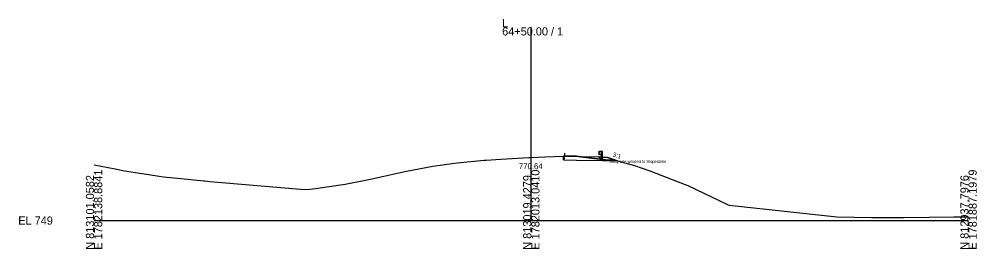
# Model space of a CAD drawing. Extents: x -26 to 7903, y -10 to 9573.
# Drawn here: x 2974.3 to 3302.8, y 5490.3 to 5569.1 of the extents above; entities that cross this region are included whole.
import ezdxf

# ---------------------------------------------------------------- set-up
doc = ezdxf.new("R2010")
doc.units = 0
for name, color, linetype in [('Exist Cross Section Cell', 7, 'Continuous'), ('Exist XS Center Line Elevation Label', 7, 'Continuous'), ('Exist XS Ground Line', 7, 'Continuous'), ('Prop XS Dump Level', 7, 'Continuous'), ('Prop XS Earthwork Shape', 7, 'Continuous'), ('Prop XS EOT Tick Mark', 7, 'Continuous'), ('Prop XS Finish Grade', 7, 'Continuous'), ('Prop XS Finish Grade Paved Shoulder', 7, 'Continuous'), ('Prop XS Finish Grade Pavement', 7, 'Continuous'), ('Prop XS Guardrail', 7, 'Continuous'), ('Prop XS Pvmt Edge Slope', 7, 'Continuous'), ('Prop XS Side Slope Text', 7, 'Continuous'), ('Prop XS Subgrade Earthwork', 7, 'Continuous'), ('Scratch_Level_3', 7, 'Continuous'), ('Scratch_Level_6', 7, 'Continuous')]:
    doc.layers.add(name, color=color, linetype=linetype)

msp = doc.modelspace()

# ---------------------------------------------------------------- linework, layer by layer
at = {"layer": 'Exist Cross Section Cell'}
for p, q in [((3150, 5500), (3150, 5566.27)), ((3000, 5500), (3150, 5500)), ((3150, 5500), (3300, 5500))]:
    msp.add_line(p, q, dxfattribs=at)
at = {"layer": 'Exist XS Ground Line'}
for p, q in [((3116.2, 5518.7), (3122.85, 5519.59)), ((3122.85, 5519.59), (3124.55, 5519.82)), ((3124.55, 5519.82), (3133.81, 5520.69)), ((3133.81, 5520.69), (3134.51, 5520.76)), ((3134.51, 5520.76), (3137.82, 5520.97)), ((3137.82, 5520.97), (3139.5, 5521.07)), ((3139.5, 5521.07), (3149.11, 5521.6)), ((3149.11, 5521.6), (3150, 5521.64)), ((3150, 5521.64), (3154.69, 5521.83)), ((3154.69, 5521.83), (3161.1, 5522.09)), ((3161.1, 5522.09), (3165.47, 5522.06)), ((3165.47, 5522.06), (3167.03, 5521.87)), ((3167.03, 5521.87), (3175.42, 5520.78)), ((3175.42, 5520.78), (3177.55, 5520.76)), ((3177.55, 5520.76), (3179.56, 5520.5)), ((3179.56, 5520.5), (3185.36, 5518.9)), ((3000, 5519.06), (3007.27, 5517.71)), ((3007.27, 5517.71), (3010.5, 5517.05)), ((3010.5, 5517.05), (3020.95, 5515.41)), ((3097.36, 5514.79), (3104.6, 5516.41)), ((3104.6, 5516.41), (3107.21, 5516.94)), ((3107.21, 5516.94), (3116.2, 5518.7)), ((3185.36, 5518.9), (3190.7, 5517.07)), ((3190.7, 5517.07), (3200.43, 5513.27)), ((3020.95, 5515.41), (3022.39, 5515.17)), ((3022.39, 5515.17), (3023.81, 5515.02)), ((3023.81, 5515.02), (3029.79, 5514.43)), ((3029.79, 5514.43), (3037.65, 5513.64)), ((3037.65, 5513.64), (3037.99, 5513.62)), ((3037.99, 5513.62), (3038.92, 5513.53)), ((3038.92, 5513.53), (3039.76, 5513.45)), ((3039.76, 5513.45), (3043.87, 5513.08)), ((3043.87, 5513.08), (3070.77, 5510.72)), ((3086.11, 5512.54), (3094.25, 5514.12)), ((3094.25, 5514.12), (3094.88, 5514.23)), ((3094.88, 5514.23), (3097.36, 5514.79)), ((3200.43, 5513.27), (3203.64, 5512.04)), ((3070.77, 5510.72), (3072.99, 5510.6)), ((3072.99, 5510.6), (3075.97, 5511.05)), ((3075.97, 5511.05), (3086.11, 5512.54)), ((3203.64, 5512.04), (3217.27, 5505.53)), ((3217.27, 5505.53), (3217.85, 5505.29)), ((3217.85, 5505.29), (3254.79, 5501.33)), ((3254.79, 5501.33), (3266.74, 5501.09)), ((3266.74, 5501.09), (3277.72, 5501.04)), ((3277.72, 5501.04), (3286.52, 5501.2)), ((3286.52, 5501.2), (3294.96, 5501.25)), ((3294.96, 5501.25), (3300, 5501.29))]:
    msp.add_line(p, q, dxfattribs=at)
at = {"layer": 'Prop XS Dump Level'}
for p, q in [((3161.14, 5521.42), (3161.47, 5521.41)), ((3161.47, 5521.41), (3161.14, 5521.42))]:
    msp.add_line(p, q, dxfattribs=at)
at = {"layer": 'Prop XS Earthwork Shape'}
msp.add_lwpolyline([(3161.1, 5520.84), (3161.47, 5520.85), (3165.47, 5520.77), (3174.38, 5520.59), (3179.56, 5520.5), (3177.55, 5520.76), (3175.42, 5520.78), (3167.03, 5521.87), (3165.47, 5522.06), (3161.1, 5522.09)], close=True, dxfattribs=at)
at = {"layer": 'Prop XS EOT Tick Mark'}
msp.add_line((3161.47, 5522.1), (3161.47, 5523.1), dxfattribs=at)
at = {"layer": 'Prop XS Finish Grade'}
for p, q in [((3173.1, 5521.87), (3176.1, 5521.63)), ((3176.1, 5521.63), (3179.56, 5520.5))]:
    msp.add_line(p, q, dxfattribs=at)
at = {"layer": 'Prop XS Finish Grade Paved Shoulder'}
msp.add_line((3161.47, 5522.1), (3173.1, 5521.87), dxfattribs=at)
at = {"layer": 'Prop XS Finish Grade Pavement'}
msp.add_line((3161.1, 5522.09), (3161.47, 5522.1), dxfattribs=at)
at = {"layer": 'Prop XS Guardrail'}
for p, q in [((3173.13, 5523.54), (3173.1, 5523.48)), ((3173.1, 5523.48), (3173.13, 5523.42)), ((3173.13, 5522.93), (3173.1, 5522.87)), ((3173.1, 5522.87), (3173.13, 5522.81)), ((3173.42, 5523.74), (3173.13, 5523.54)), ((3173.13, 5523.42), (3173.42, 5523.22)), ((3173.42, 5523.13), (3173.13, 5522.93)), ((3173.13, 5522.81), (3173.42, 5522.61)), ((3173.92, 5523.74), (3173.42, 5523.74)), ((3173.42, 5523.22), (3173.42, 5523.13)), ((3174.42, 5523.74), (3173.92, 5523.74)), ((3173.92, 5523.74), (3173.92, 5521.24)), ((3174.42, 5521.24), (3174.42, 5523.74)), ((3173.42, 5522.61), (3173.92, 5522.61))]:
    msp.add_line(p, q, dxfattribs=at)
at = {"layer": 'Prop XS Pvmt Edge Slope'}
msp.add_line((3173.1, 5521.87), (3174.38, 5520.59), dxfattribs=at)
at = {"layer": 'Prop XS Subgrade Earthwork'}
for p, q in [((3161.1, 5520.84), (3161.1, 5522.09)), ((3161.1, 5520.84), (3161.47, 5520.85)), ((3161.47, 5520.85), (3165.47, 5520.77)), ((3165.47, 5520.77), (3174.38, 5520.59)), ((3174.38, 5520.59), (3179.56, 5520.5))]:
    msp.add_line(p, q, dxfattribs=at)
at = {"layer": 'Scratch_Level_3'}
for p, q in [((3176.1, 5521.63), (3173.1, 5521.87)), ((3173.1, 5521.87), (3174.38, 5520.59)), ((3174.38, 5520.59), (3179.56, 5520.5)), ((3179.56, 5520.5), (3176.1, 5521.63))]:
    msp.add_line(p, q, dxfattribs=at)
at = {"layer": 'Scratch_Level_6'}
for points in [[(3161.1, 5520.84), (3161.47, 5520.85), (3165.47, 5520.77), (3174.38, 5520.59), (3179.56, 5520.5), (3177.55, 5520.76), (3175.42, 5520.78), (3167.03, 5521.87), (3165.84, 5522.02), (3162.68, 5522.08), (3161.1, 5522.09)], [(3162.68, 5522.08), (3165.84, 5522.02), (3165.47, 5522.06)]]:
    msp.add_lwpolyline(points, close=True, dxfattribs=at)

# ---------------------------------------------------------------- texts
at = {"layer": 'Exist Cross Section Cell'}
for s, p in [('L', (3140, 5566.27)), ('64+50.00 / 1', (3140, 5563.47)), ('EL 749', (2974, 5498.6))]:
    msp.add_text(s, height=2.8, dxfattribs=at).set_placement(p)
for s, p in [('E 1782138.8841', (3002.8, 5490)), ('E 1782013.0410', (3152.8, 5490)), ('E 1781887.1979', (3302.8, 5490)), ('N 813101.0582', (3000, 5490)), ('N 813019.4279', (3150, 5490)), ('N 812937.7976', (3300, 5490))]:
    msp.add_text(s, height=2.8, rotation=90, dxfattribs=at).set_placement(p)
at = {"layer": 'Exist XS Center Line Elevation Label'}
msp.add_text('770.64', height=2, dxfattribs=at).set_placement((3145.72, 5517.64))
at = {"layer": 'Prop XS Dump Level'}
for s, height, p in [('Eop', 0.3, (3161.1, 5521.79)), ('Case4', 0.04, (3173.47, 5521.52)), ('Subgrade warped to Slopestake', 1, (3176.66, 5519.77))]:
    msp.add_text(s, height=height, dxfattribs=at).set_placement(p)
at = {"layer": 'Prop XS Side Slope Text'}
msp.add_text('3:1', height=1.5, rotation=341.9322, dxfattribs=at).set_placement((3177.8, 5522.05))

doc.saveas('drawing.dxf')
